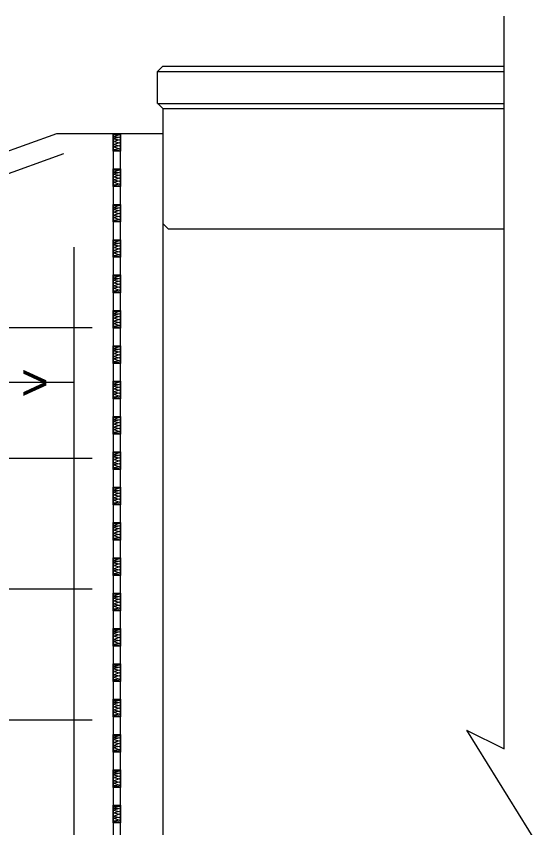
# Model space of a CAD drawing. Extents: x -0.08 to 2.83, y -0.03 to 1.92.
# Drawn here: x 0.8 to 0.9292, y 0.3319 to 0.5312 of the extents above; entities that cross this region are included whole.
import ezdxf

# ---------------------------------------------------------------- set-up
doc = ezdxf.new("R2010")
doc.units = 0
for name, color, linetype in [('1', 7, 'Continuous'), ('50', 7, 'Continuous'), ('51', 7, 'Continuous'), ('55', 7, 'Continuous')]:
    doc.layers.add(name, color=color, linetype=linetype)

msp = doc.modelspace()

# ---------------------------------------------------------------- linework, layer by layer
at = {"layer": '1'}
for points in [[(0.82387, 0.49802), (0.82387, 0.50235), (0.82561, 0.50235), (0.82561, 0.49802)], [(0.82387, 0.48934), (0.82387, 0.49368), (0.82561, 0.49368), (0.82561, 0.48934)], [(0.82387, 0.48066), (0.82387, 0.48499), (0.82561, 0.48499), (0.82561, 0.48066)], [(0.82387, 0.47198), (0.82387, 0.47631), (0.82561, 0.47631), (0.82561, 0.47198)], [(0.82387, 0.46329), (0.82387, 0.46764), (0.82561, 0.46764), (0.82561, 0.46329)], [(0.82387, 0.45462), (0.82387, 0.45895), (0.82561, 0.45895), (0.82561, 0.45462)], [(0.82387, 0.44594), (0.82387, 0.45027), (0.82561, 0.45027), (0.82561, 0.44594)], [(0.82387, 0.43725), (0.82387, 0.44159), (0.82561, 0.44159), (0.82561, 0.43725)], [(0.82387, 0.42858), (0.82387, 0.43291), (0.82561, 0.43291), (0.82561, 0.42858)], [(0.82387, 0.41989), (0.82387, 0.42423), (0.82561, 0.42423), (0.82561, 0.41989)], [(0.82387, 0.41121), (0.82387, 0.41555), (0.82561, 0.41555), (0.82561, 0.41121)], [(0.82387, 0.40254), (0.82387, 0.40687), (0.82561, 0.40687), (0.82561, 0.40254)], [(0.82387, 0.39385), (0.82387, 0.39819), (0.82561, 0.39819), (0.82561, 0.39385)], [(0.82387, 0.38517), (0.82387, 0.38951), (0.82561, 0.38951), (0.82561, 0.38517)], [(0.82387, 0.37649), (0.82387, 0.38083), (0.82561, 0.38083), (0.82561, 0.37649)], [(0.82387, 0.36781), (0.82387, 0.37214), (0.82561, 0.37214), (0.82561, 0.36781)], [(0.82387, 0.35913), (0.82387, 0.36347), (0.82561, 0.36347), (0.82561, 0.35913)], [(0.82387, 0.35045), (0.82387, 0.35479), (0.82561, 0.35479), (0.82561, 0.35045)], [(0.82387, 0.34177), (0.82387, 0.3461), (0.82561, 0.3461), (0.82561, 0.34177)], [(0.82387, 0.33309), (0.82387, 0.33743), (0.82561, 0.33743), (0.82561, 0.33309)]]:
    msp.add_lwpolyline(points, close=True, dxfattribs=at)
for points in [[(0.82398, 0.50211), (0.82551, 0.50213), (0.82398, 0.50161), (0.82534, 0.50149), (0.82403, 0.50109), (0.82531, 0.50082), (0.82406, 0.50041), (0.82527, 0.50012), (0.82406, 0.49967), (0.82537, 0.49934), (0.82401, 0.4991), (0.82537, 0.49861), (0.82409, 0.49838), (0.82531, 0.49826), (0.82525, 0.49824)], [(0.82398, 0.49343), (0.82551, 0.49344), (0.82398, 0.49293), (0.82534, 0.49281), (0.82403, 0.4924), (0.82531, 0.49214), (0.82406, 0.49174), (0.82527, 0.49144), (0.82406, 0.49099), (0.82537, 0.49066), (0.82401, 0.49043), (0.82537, 0.48993), (0.82409, 0.48969), (0.82531, 0.48958), (0.82525, 0.48956)], [(0.82398, 0.48475), (0.82551, 0.48477), (0.82398, 0.48424), (0.82534, 0.48413), (0.82403, 0.48373), (0.82531, 0.48346), (0.82406, 0.48305), (0.82527, 0.48276), (0.82406, 0.48231), (0.82537, 0.48199), (0.82401, 0.48174), (0.82537, 0.48125), (0.82409, 0.48101), (0.82531, 0.48089), (0.82525, 0.48088)], [(0.82398, 0.47607), (0.82551, 0.47609), (0.82398, 0.47557), (0.82534, 0.47545), (0.82403, 0.47504), (0.82531, 0.47478), (0.82406, 0.47437), (0.82527, 0.47408), (0.82406, 0.47363), (0.82537, 0.4733), (0.82401, 0.47306), (0.82537, 0.47257), (0.82409, 0.47234), (0.82531, 0.47222), (0.82525, 0.4722)], [(0.82398, 0.46739), (0.82551, 0.4674), (0.82398, 0.46689), (0.82534, 0.46677), (0.82403, 0.46636), (0.82531, 0.46609), (0.82406, 0.46569), (0.82527, 0.4654), (0.82406, 0.46495), (0.82537, 0.46462), (0.82401, 0.46439), (0.82537, 0.46389), (0.82409, 0.46365), (0.82531, 0.46354), (0.82525, 0.46352)], [(0.82398, 0.45871), (0.82551, 0.45873), (0.82398, 0.4582), (0.82534, 0.45809), (0.82403, 0.45769), (0.82531, 0.45742), (0.82406, 0.45701), (0.82527, 0.45672), (0.82406, 0.45627), (0.82537, 0.45594), (0.82401, 0.4557), (0.82537, 0.45521), (0.82409, 0.45497), (0.82531, 0.45485), (0.82525, 0.45484)], [(0.82398, 0.45003), (0.82551, 0.45004), (0.82398, 0.44953), (0.82534, 0.44941), (0.82403, 0.449), (0.82531, 0.44874), (0.82406, 0.44834), (0.82527, 0.44804), (0.82406, 0.44759), (0.82537, 0.44726), (0.82401, 0.44702), (0.82537, 0.44653), (0.82409, 0.44629), (0.82531, 0.44618), (0.82525, 0.44616)], [(0.82398, 0.44135), (0.82551, 0.44137), (0.82398, 0.44084), (0.82534, 0.44073), (0.82403, 0.44032), (0.82531, 0.44005), (0.82406, 0.43965), (0.82527, 0.43936), (0.82406, 0.43891), (0.82537, 0.43858), (0.82401, 0.43834), (0.82537, 0.43785), (0.82409, 0.43761), (0.82531, 0.43749), (0.82525, 0.43748)], [(0.82398, 0.43267), (0.82551, 0.43269), (0.82398, 0.43216), (0.82534, 0.43204), (0.82403, 0.43164), (0.82531, 0.43138), (0.82406, 0.43097), (0.82527, 0.43068), (0.82406, 0.43023), (0.82537, 0.4299), (0.82401, 0.42966), (0.82537, 0.42917), (0.82409, 0.42893), (0.82531, 0.42881), (0.82525, 0.42879)], [(0.82398, 0.42399), (0.82551, 0.424), (0.82398, 0.42349), (0.82534, 0.42337), (0.82403, 0.42296), (0.82531, 0.42269), (0.82406, 0.42229), (0.82527, 0.42199), (0.82406, 0.42154), (0.82537, 0.42122), (0.82401, 0.42098), (0.82537, 0.42049), (0.82409, 0.42025), (0.82531, 0.42014), (0.82525, 0.42012)], [(0.82398, 0.41531), (0.82551, 0.41533), (0.82398, 0.4148), (0.82534, 0.41469), (0.82403, 0.41428), (0.82531, 0.41401), (0.82406, 0.41361), (0.82527, 0.41332), (0.82406, 0.41287), (0.82537, 0.41254), (0.82401, 0.4123), (0.82537, 0.41181), (0.82409, 0.41157), (0.82531, 0.41145), (0.82525, 0.41144)], [(0.82398, 0.40663), (0.82551, 0.40664), (0.82398, 0.40612), (0.82534, 0.406), (0.82403, 0.4056), (0.82531, 0.40534), (0.82406, 0.40493), (0.82527, 0.40464), (0.82406, 0.40419), (0.82537, 0.40386), (0.82401, 0.40362), (0.82537, 0.40313), (0.82409, 0.40289), (0.82531, 0.40277), (0.82525, 0.40275)], [(0.82398, 0.39794), (0.82551, 0.39796), (0.82398, 0.39744), (0.82534, 0.39733), (0.82403, 0.39692), (0.82531, 0.39665), (0.82406, 0.39625), (0.82527, 0.39595), (0.82406, 0.3955), (0.82537, 0.39518), (0.82401, 0.39494), (0.82537, 0.39444), (0.82409, 0.39421), (0.82531, 0.39409), (0.82525, 0.39408)], [(0.82398, 0.38927), (0.82551, 0.38929), (0.82398, 0.38876), (0.82534, 0.38864), (0.82403, 0.38824), (0.82531, 0.38797), (0.82406, 0.38757), (0.82527, 0.38728), (0.82406, 0.38683), (0.82537, 0.38649), (0.82401, 0.38626), (0.82537, 0.38577), (0.82409, 0.38553), (0.82531, 0.38541), (0.82525, 0.38539)], [(0.82398, 0.38059), (0.82551, 0.3806), (0.82398, 0.38008), (0.82534, 0.37996), (0.82403, 0.37956), (0.82531, 0.37929), (0.82406, 0.37889), (0.82527, 0.37859), (0.82406, 0.37814), (0.82537, 0.37782), (0.82401, 0.37758), (0.82537, 0.37709), (0.82409, 0.37684), (0.82531, 0.37673), (0.82525, 0.37671)], [(0.82398, 0.3719), (0.82551, 0.37192), (0.82398, 0.3714), (0.82534, 0.37129), (0.82403, 0.37088), (0.82531, 0.37061), (0.82406, 0.37021), (0.82527, 0.36991), (0.82406, 0.36946), (0.82537, 0.36914), (0.82401, 0.36889), (0.82537, 0.3684), (0.82409, 0.36817), (0.82531, 0.36805), (0.82525, 0.36804)], [(0.82398, 0.36323), (0.82551, 0.36324), (0.82398, 0.36272), (0.82534, 0.3626), (0.82403, 0.36219), (0.82531, 0.36193), (0.82406, 0.36153), (0.82527, 0.36124), (0.82406, 0.36079), (0.82537, 0.36045), (0.82401, 0.36022), (0.82537, 0.35973), (0.82409, 0.35949), (0.82531, 0.35937), (0.82525, 0.35935)], [(0.82398, 0.35454), (0.82551, 0.35456), (0.82398, 0.35404), (0.82534, 0.35392), (0.82403, 0.35352), (0.82531, 0.35325), (0.82406, 0.35284), (0.82527, 0.35255), (0.82406, 0.3521), (0.82537, 0.35178), (0.82401, 0.35154), (0.82537, 0.35104), (0.82409, 0.3508), (0.82531, 0.35069), (0.82525, 0.35067)], [(0.82398, 0.34586), (0.82551, 0.34588), (0.82398, 0.34536), (0.82534, 0.34524), (0.82403, 0.34484), (0.82531, 0.34457), (0.82406, 0.34417), (0.82527, 0.34387), (0.82406, 0.34342), (0.82537, 0.34309), (0.82401, 0.34285), (0.82537, 0.34236), (0.82409, 0.34213), (0.82531, 0.34201), (0.82525, 0.34199)], [(0.82398, 0.33719), (0.82551, 0.3372), (0.82398, 0.33668), (0.82534, 0.33656), (0.82403, 0.33615), (0.82531, 0.33589), (0.82406, 0.33549), (0.82527, 0.33519), (0.82406, 0.33474), (0.82537, 0.33441), (0.82401, 0.33418), (0.82537, 0.33369), (0.82409, 0.33344), (0.82531, 0.33333), (0.82525, 0.33331)]]:
    msp.add_lwpolyline(points, dxfattribs=at)
at = {"layer": '50'}
for p, q in [((0.91992, 0.35121), (0.91992, 0.5312)), ((0.83601, 0.51892), (0.83469, 0.51759)), ((0.83601, 0.51892), (0.91992, 0.51892)), ((0.83467, 0.51761), (0.83467, 0.5098)), ((0.83467, 0.51761), (0.91992, 0.51761)), ((0.83601, 0.5085), (0.83469, 0.50982)), ((0.83474, 0.5098), (0.91992, 0.5098)), ((0.83601, 0.5085), (0.83601, 0.18731)), ((0.83601, 0.5085), (0.91992, 0.5085)), ((0.36956, 0.34269), (0.80997, 0.50242)), ((0.80997, 0.50242), (0.83601, 0.50242)), ((0.82386, 0.50242), (0.82386, 0.49773)), ((0.82559, 0.50242), (0.82559, 0.49773)), ((0.82559, 0.50192), (0.82559, 0.49773)), ((0.37071, 0.33757), (0.81174, 0.49752)), ((0.82386, 0.49773), (0.82386, 0.41832)), ((0.82559, 0.49773), (0.82559, 0.41832)), ((0.82386, 0.49374), (0.82386, 0.48904)), ((0.82559, 0.49374), (0.82559, 0.48904)), ((0.82559, 0.49324), (0.82559, 0.48904)), ((0.82386, 0.48904), (0.82386, 0.48829)), ((0.82559, 0.48904), (0.82559, 0.48829)), ((0.82386, 0.48569), (0.82386, 0.47961)), ((0.82386, 0.48505), (0.82386, 0.48036)), ((0.82559, 0.48569), (0.82559, 0.47961)), ((0.82559, 0.48505), (0.82559, 0.48036)), ((0.82559, 0.48456), (0.82559, 0.48036)), ((0.82386, 0.48036), (0.82386, 0.47961)), ((0.82559, 0.48036), (0.82559, 0.47961)), ((0.83731, 0.47899), (0.83601, 0.48028)), ((0.83731, 0.47899), (0.91992, 0.47899)), ((0.82386, 0.47701), (0.82386, 0.47093)), ((0.82386, 0.47701), (0.82386, 0.47093)), ((0.82559, 0.47701), (0.82559, 0.47093)), ((0.82559, 0.47701), (0.82559, 0.47093)), ((0.82386, 0.47638), (0.82386, 0.47169)), ((0.82559, 0.47638), (0.82559, 0.47169)), ((0.82559, 0.47588), (0.82559, 0.47169)), ((0.82386, 0.47169), (0.82386, 0.47093)), ((0.82559, 0.47169), (0.82559, 0.47093)), ((0.82386, 0.46834), (0.82386, 0.46224)), ((0.82386, 0.46834), (0.82386, 0.46224)), ((0.82386, 0.46834), (0.82386, 0.46224)), ((0.82386, 0.46769), (0.82386, 0.463)), ((0.82559, 0.46834), (0.82559, 0.46224)), ((0.82559, 0.46834), (0.82559, 0.46224)), ((0.82559, 0.46834), (0.82559, 0.46224)), ((0.82559, 0.46769), (0.82559, 0.463)), ((0.82559, 0.46719), (0.82559, 0.463)), ((0.82386, 0.463), (0.82386, 0.46224)), ((0.82559, 0.463), (0.82559, 0.46224)), ((0.82386, 0.45901), (0.82386, 0.45432)), ((0.82559, 0.45901), (0.82559, 0.45432)), ((0.82559, 0.45852), (0.82559, 0.45432)), ((0.82386, 0.45432), (0.82386, 0.45357)), ((0.82559, 0.45432), (0.82559, 0.45357)), ((0.82386, 0.45097), (0.82386, 0.44489)), ((0.82559, 0.45097), (0.82559, 0.44489)), ((0.82386, 0.45034), (0.82386, 0.44564)), ((0.82559, 0.45034), (0.82559, 0.44564)), ((0.82559, 0.44984), (0.82559, 0.44564)), ((0.82386, 0.44564), (0.82386, 0.44489)), ((0.82559, 0.44564), (0.82559, 0.44489)), ((0.82386, 0.44229), (0.82386, 0.4362)), ((0.82386, 0.44229), (0.82386, 0.4362)), ((0.82386, 0.44165), (0.82386, 0.43696)), ((0.82559, 0.44229), (0.82559, 0.4362)), ((0.82559, 0.44229), (0.82559, 0.4362)), ((0.82559, 0.44165), (0.82559, 0.43696)), ((0.82559, 0.44115), (0.82559, 0.43696)), ((0.82386, 0.43696), (0.82386, 0.4362)), ((0.82559, 0.43696), (0.82559, 0.4362)), ((0.82386, 0.43361), (0.82386, 0.42753)), ((0.82386, 0.43361), (0.82386, 0.42753)), ((0.82386, 0.43361), (0.82386, 0.42753)), ((0.82386, 0.43297), (0.82386, 0.42828)), ((0.82559, 0.43361), (0.82559, 0.42753)), ((0.82559, 0.43361), (0.82559, 0.42753)), ((0.82559, 0.43361), (0.82559, 0.42753)), ((0.82559, 0.43297), (0.82559, 0.42828)), ((0.82559, 0.43248), (0.82559, 0.42828)), ((0.82386, 0.42828), (0.82386, 0.42753)), ((0.82559, 0.42828), (0.82559, 0.42753)), ((0.82386, 0.42429), (0.82386, 0.4196)), ((0.82559, 0.42429), (0.82559, 0.4196)), ((0.82559, 0.42379), (0.82559, 0.4196)), ((0.82386, 0.4196), (0.82386, 0.41884)), ((0.82559, 0.4196), (0.82559, 0.41884)), ((0.82386, 0.41832), (0.82386, 0.18731)), ((0.82559, 0.41832), (0.82559, 0.18725)), ((0.82386, 0.41625), (0.82386, 0.41016)), ((0.82386, 0.41561), (0.82386, 0.41092)), ((0.82559, 0.41625), (0.82559, 0.41016)), ((0.82559, 0.41561), (0.82559, 0.41092)), ((0.82559, 0.41511), (0.82559, 0.41092)), ((0.82386, 0.41092), (0.82386, 0.41016)), ((0.82559, 0.41092), (0.82559, 0.41016)), ((0.82386, 0.40757), (0.82386, 0.40149)), ((0.82386, 0.40757), (0.82386, 0.40149)), ((0.82386, 0.40693), (0.82386, 0.40224)), ((0.82559, 0.40757), (0.82559, 0.40149)), ((0.82559, 0.40757), (0.82559, 0.40149)), ((0.82559, 0.40693), (0.82559, 0.40224)), ((0.82559, 0.40644), (0.82559, 0.40224)), ((0.82386, 0.40224), (0.82386, 0.40149)), ((0.82559, 0.40224), (0.82559, 0.40149)), ((0.82386, 0.39889), (0.82386, 0.3928)), ((0.82386, 0.39889), (0.82386, 0.3928)), ((0.82386, 0.39889), (0.82386, 0.3928)), ((0.82559, 0.39889), (0.82559, 0.3928)), ((0.82559, 0.39889), (0.82559, 0.3928)), ((0.82559, 0.39889), (0.82559, 0.3928)), ((0.82386, 0.39825), (0.82386, 0.39356)), ((0.82559, 0.39825), (0.82559, 0.39356)), ((0.82559, 0.39775), (0.82559, 0.39356)), ((0.82386, 0.39356), (0.82386, 0.3928)), ((0.82559, 0.39356), (0.82559, 0.3928)), ((0.82386, 0.38957), (0.82386, 0.38488)), ((0.82559, 0.38957), (0.82559, 0.38488)), ((0.82559, 0.38907), (0.82559, 0.38488)), ((0.82386, 0.38488), (0.82386, 0.38412)), ((0.82559, 0.38488), (0.82559, 0.38412)), ((0.82386, 0.38153), (0.82386, 0.37544)), ((0.82386, 0.38089), (0.82386, 0.37619)), ((0.82559, 0.38153), (0.82559, 0.37544)), ((0.82559, 0.38089), (0.82559, 0.37619)), ((0.82559, 0.38039), (0.82559, 0.37619)), ((0.82386, 0.37619), (0.82386, 0.37544)), ((0.82559, 0.37619), (0.82559, 0.37544)), ((0.82386, 0.37284), (0.82386, 0.36676)), ((0.82386, 0.37284), (0.82386, 0.36676)), ((0.82559, 0.37284), (0.82559, 0.36676)), ((0.82559, 0.37284), (0.82559, 0.36676)), ((0.82386, 0.37221), (0.82386, 0.36752)), ((0.82559, 0.37221), (0.82559, 0.36752)), ((0.82559, 0.37171), (0.82559, 0.36752)), ((0.82386, 0.36752), (0.82386, 0.36676)), ((0.82559, 0.36752), (0.82559, 0.36676)), ((0.82386, 0.36417), (0.82386, 0.35808)), ((0.82386, 0.36417), (0.82386, 0.35808)), ((0.82386, 0.36417), (0.82386, 0.35808)), ((0.82386, 0.36353), (0.82386, 0.35884)), ((0.82559, 0.36417), (0.82559, 0.35808)), ((0.82559, 0.36417), (0.82559, 0.35808)), ((0.82559, 0.36417), (0.82559, 0.35808)), ((0.82559, 0.36353), (0.82559, 0.35884)), ((0.82559, 0.36303), (0.82559, 0.35884)), ((0.82386, 0.35884), (0.82386, 0.35808)), ((0.82559, 0.35884), (0.82559, 0.35808)), ((0.82386, 0.35484), (0.82386, 0.35015)), ((0.82559, 0.35484), (0.82559, 0.35015)), ((0.82559, 0.35435), (0.82559, 0.35015)), ((0.82386, 0.35015), (0.82386, 0.3494)), ((0.82559, 0.35015), (0.82559, 0.3494)), ((0.82386, 0.3468), (0.82386, 0.34072)), ((0.82386, 0.34617), (0.82386, 0.34148)), ((0.82559, 0.3468), (0.82559, 0.34072)), ((0.82559, 0.34617), (0.82559, 0.34148)), ((0.82559, 0.34567), (0.82559, 0.34148)), ((0.82386, 0.34148), (0.82386, 0.34072)), ((0.82559, 0.34148), (0.82559, 0.34072)), ((0.82386, 0.33813), (0.82386, 0.33204)), ((0.82386, 0.33813), (0.82386, 0.33204)), ((0.82386, 0.33749), (0.82386, 0.33279)), ((0.82559, 0.33813), (0.82559, 0.33204)), ((0.82559, 0.33813), (0.82559, 0.33204)), ((0.82559, 0.33749), (0.82559, 0.33279)), ((0.82559, 0.33699), (0.82559, 0.33279)), ((0.82386, 0.33279), (0.82386, 0.33204)), ((0.82559, 0.33279), (0.82559, 0.33204))]:
    msp.add_line(p, q, dxfattribs=at)
at = {"layer": '51'}
for p, q in [((0.81422, 0.16127), (0.81422, 0.47444)), ((0.81865, 0.45467), (0.68924, 0.45467)), ((0.81865, 0.42255), (0.6013, 0.42255)), ((0.81865, 0.39044), (0.51335, 0.39044)), ((0.81865, 0.35832), (0.42799, 0.35832))]:
    msp.add_line(p, q, dxfattribs=at)
at = {"layer": '55'}
for p, q in [((0.70674, 0.44133), (0.81422, 0.44133)), ((0.91067, 0.35583), (0.91992, 0.35121)), ((0.91067, 0.35583), (0.92917, 0.326))]:
    msp.add_line(p, q, dxfattribs=at)

# ---------------------------------------------------------------- texts
msp.add_text('>', height=0.00868, dxfattribs=at).set_placement((0.8012, 0.43699))
msp.add_text('>', height=0.00868, dxfattribs=at).set_placement((0.8012, 0.43699))

doc.saveas('drawing.dxf')
